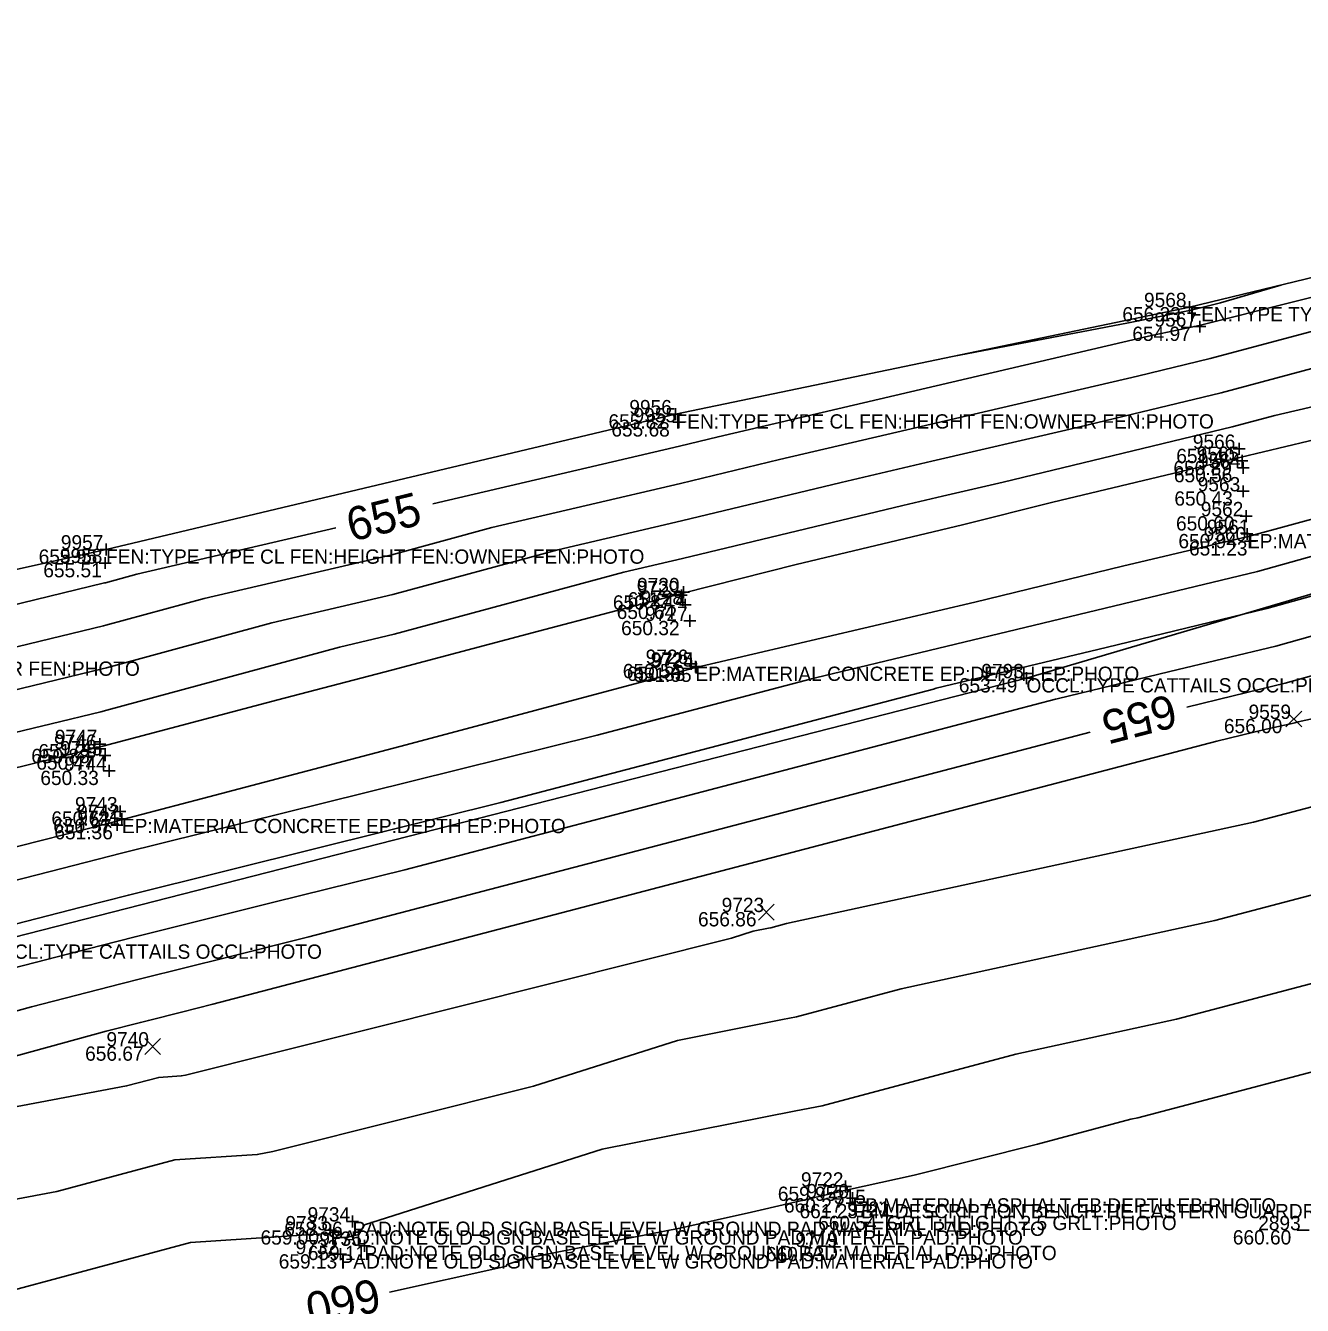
# Model space of a CAD drawing. Extents: x 2129350 to 2137777, y 657588 to 659885.
# Drawn here: x 2134161.5 to 2134268.7, y 659078.5 to 659185.9 of the extents above; entities that cross this region are included whole.
import ezdxf

# ---------------------------------------------------------------- set-up
doc = ezdxf.new("R2010")
doc.units = 0
for name, color, linetype in [('DT_X_Contour_Major', 7, 'Continuous'), ('DT_X_Contour_Minor', 7, 'Continuous'), ('DT_X_TIN_Hull', 7, 'Continuous'), ('SV_X_Occupation_Line', 7, 'Continuous'), ('SV_X_Random_Point', 7, 'Continuous'), ('SV_X_Shot_Marker', 7, 'Continuous'), ('SV_X_Text_Comment', 7, 'Continuous'), ('SV_X_Text_Elevation', 7, 'Continuous'), ('SV_X_Text_Name', 7, 'Continuous')]:
    doc.layers.add(name, color=color, linetype=linetype)

msp = doc.modelspace()

# ---------------------------------------------------------------- linework, layer by layer
at = {"layer": 'DT_X_Contour_Major'}
for points in [[(2134195.69, 659145.79), (2134216.4, 659150.64), (2134219.64, 659151.42), (2134235.81, 659155.2), (2134255.8, 659159.88), (2134260.05, 659160.76), (2134275.77, 659164.7), (2134292.78, 659169.65)], [(2134259.01, 659128.73), (2134262.9, 659129.67), (2134267.26, 659130.72), (2134272.2, 659132.1), (2134312.05, 659141.85), (2134315.24, 659142.75), (2134318.55, 659143.54), (2134356.18, 659152.33)], [(2134090.41, 659120), (2134090.8, 659120.09), (2134110.11, 659125.11), (2134111.21, 659125.37), (2134125.33, 659128.79), (2134129.5, 659129.8), (2134143.7, 659133.23), (2134147.32, 659134.1), (2134168.13, 659139.15), (2134168.2, 659139.17), (2134170.82, 659139.88), (2134187.54, 659143.78)], [(2134154.12, 659101.39), (2134162, 659103.56), (2134169.48, 659105.48), (2134171.25, 659105.93), (2134178.46, 659107.72), (2134185.28, 659109.42), (2134250.89, 659126.62)], [(2134192.04, 659079.6), (2134201.65, 659081.72), (2134201.85, 659081.78), (2134201.93, 659081.92), (2134203.56, 659082.44), (2134216.42, 659084.98), (2134222.44, 659086.3), (2134228.12, 659087.64), (2134230.5, 659088.18), (2134236.1, 659089.42), (2134246.48, 659092.02), (2134254.29, 659094.11), (2134254.9, 659094.24), (2134275.91, 659099.77), (2134289.22, 659102.85)]]:
    msp.add_lwpolyline(points, dxfattribs=at)
at = {"layer": 'DT_X_Contour_Minor'}
for points in [[(2134152.76, 659131.84), (2134168.03, 659135.54), (2134168.24, 659135.6), (2134176.5, 659137.84), (2134192.24, 659141.51), (2134200.65, 659143.79), (2134216.49, 659147.5), (2134224.81, 659149.5), (2134236.7, 659152.28), (2134254.85, 659156.52), (2134260.96, 659157.99), (2134275.77, 659161.94), (2134280.7, 659163.09), (2134300.56, 659168.43), (2134304.69, 659169.39), (2134308.74, 659170.44), (2134312.54, 659171.55), (2134332.75, 659176.79), (2134336.49, 659177.87), (2134356.95, 659183.17)], [(2134357, 659180.03), (2134343.97, 659176.66), (2134332.83, 659173.43), (2134320.38, 659170.2), (2134309.2, 659166.94), (2134306.79, 659166.32), (2134294.71, 659163.52), (2134282.62, 659160.26), (2134271.08, 659157.58), (2134261.88, 659155.12), (2134249.21, 659152.07), (2134237.6, 659149.36), (2134229.99, 659147.58), (2134216.57, 659144.35), (2134206.19, 659141.92), (2134192.34, 659138.17), (2134182.17, 659135.8), (2134168.28, 659132.03), (2134167.92, 659131.93), (2134158.21, 659129.58)], [(2134357.06, 659176.9), (2134351.46, 659175.45), (2134332.91, 659170.07), (2134328.21, 659168.85), (2134309.66, 659163.45), (2134308.89, 659163.25), (2134288.86, 659158.6), (2134284.53, 659157.44), (2134266.4, 659153.21), (2134262.8, 659152.25), (2134243.57, 659147.62), (2134238.49, 659146.44), (2134235.17, 659145.66), (2134216.66, 659141.21), (2134211.73, 659140.06), (2134192.45, 659134.84), (2134187.85, 659133.76), (2134168.32, 659128.46), (2134167.81, 659128.32), (2134163.65, 659127.32), (2134143.51, 659122.48)], [(2134354.27, 659172.9), (2134335.82, 659167.99), (2134332.96, 659167.27), (2134312.59, 659161.84), (2134310.18, 659161.23), (2134308.22, 659160.74), (2134295.76, 659157.65), (2134289.27, 659156.02), (2134287.68, 659155.64), (2134269.19, 659151.04), (2134263.57, 659149.7), (2134247.74, 659145.92), (2134240.17, 659144.03), (2134226.21, 659140.7), (2134216.67, 659138.28), (2134216.49, 659138.23), (2134204.56, 659135.1), (2134192.21, 659131.83), (2134182.68, 659129.32), (2134167.97, 659125.44), (2134167.73, 659125.38), (2134163.65, 659124.36), (2134152.8, 659121.69)], [(2134149.54, 659114.15), (2134168.53, 659118.99), (2134169.51, 659119.25), (2134176.36, 659121.06), (2134193.45, 659125.56), (2134215.07, 659131.32), (2134217.44, 659131.95), (2134217.78, 659132.04), (2134219.45, 659132.44), (2134241.19, 659137.52), (2134253.61, 659140.56), (2134264.15, 659143.06), (2134281.64, 659147.81), (2134287.19, 659149.33), (2134309.81, 659155.46), (2134311.1, 659155.81), (2134317.07, 659157.39), (2134335.2, 659162.28), (2134338.65, 659163.23), (2134359.31, 659168.81)], [(2134143.24, 659109.7), (2134164.52, 659115.16), (2134169.55, 659116.45), (2134190.08, 659121.55), (2134209.48, 659126.37), (2134227.5, 659131.1), (2134227.81, 659131.17), (2134246.92, 659135.78), (2134264.95, 659140.12), (2134285.42, 659145.84), (2134292.96, 659147.69), (2134312.13, 659153.08), (2134332.05, 659157.88), (2134341.43, 659160.07), (2134360.86, 659164.73)], [(2134239.34, 659158.16), (2134254.1, 659160.98), (2134259.36, 659162.06), (2134261.82, 659162.68), (2134266.91, 659164.16)], [(2134149.49, 659107.65), (2134166.17, 659111.93), (2134170.12, 659112.94), (2134186.21, 659116.94), (2134201.41, 659120.72), (2134237.74, 659130.24), (2134237.97, 659130.3), (2134252.24, 659133.74), (2134265.72, 659136.99), (2134281.01, 659141.26), (2134299.32, 659145.74), (2134313.17, 659149.64), (2134327.55, 659153.1), (2134348.69, 659158.03), (2134362.22, 659161.28)], [(2134155.75, 659105.6), (2134167.83, 659108.7), (2134170.68, 659109.44), (2134182.33, 659112.33), (2134193.34, 659115.07), (2134247.98, 659129.39), (2134248.13, 659129.43), (2134257.57, 659131.71), (2134266.49, 659133.85), (2134276.6, 659136.68), (2134305.69, 659143.8), (2134314.2, 659146.19), (2134323.05, 659148.32), (2134355.95, 659156)], [(2134127.59, 659090.34), (2134168.25, 659101.51), (2134171.13, 659102.25), (2134171.81, 659102.42), (2134174.59, 659103.11), (2134177.21, 659103.77), (2134261.53, 659125.87), (2134265.68, 659126.88), (2134267.84, 659127.35), (2134268.08, 659127.41), (2134268.35, 659127.48), (2134314.46, 659137.47), (2134316.66, 659137.98), (2134316.74, 659138), (2134318.98, 659138.61), (2134362.91, 659148.03)], [(2134154.98, 659094.1), (2134169.97, 659096.91), (2134172.67, 659097.63), (2134174.56, 659097.76), (2134174.91, 659097.83), (2134220.76, 659109.32), (2134222.58, 659109.9), (2134223.89, 659110.16), (2134224.07, 659110.19), (2134225.39, 659110.54), (2134264.61, 659119.07), (2134270.04, 659120.5), (2134276.27, 659121.94), (2134310.98, 659129.47), (2134318.67, 659131.25), (2134318.92, 659131.31), (2134326.75, 659133.45), (2134359.46, 659140.46)], [(2134127.31, 659081.14), (2134164.1, 659088.04), (2134174.01, 659090.7), (2134180.94, 659091.15), (2134182.24, 659091.4), (2134204.15, 659096.9), (2134216.24, 659100.74), (2134225.04, 659102.48), (2134226.23, 659102.72), (2134235.02, 659105.07), (2134261.37, 659110.8), (2134272, 659113.59), (2134284.19, 659116.41), (2134307.5, 659121.46), (2134320.67, 659124.52), (2134321.1, 659124.62), (2134334.51, 659128.28), (2134356.01, 659132.89)], [(2134158.23, 659079.17), (2134175.35, 659083.76), (2134186.81, 659084.51), (2134186.86, 659084.53), (2134187.34, 659084.2), (2134188.45, 659084.18), (2134189.48, 659084.43), (2134189.96, 659085.24), (2134209.9, 659091.59), (2134226.18, 659094.81), (2134228.38, 659095.24), (2134244.66, 659099.59), (2134258.14, 659102.52), (2134273.96, 659106.68), (2134292.11, 659110.88), (2134304.02, 659113.46), (2134322.68, 659117.79), (2134323.28, 659117.93), (2134342.28, 659123.12), (2134352.56, 659125.32)]]:
    msp.add_lwpolyline(points, dxfattribs=at)
at = {"layer": 'DT_X_TIN_Hull'}
msp.add_lwpolyline([(2134356.03, 659185.95), (2134303.52, 659173.01), (2134259.23, 659162.31), (2134216.07, 659153.31), (2134168.25, 659141.96), (2134125.88, 659132.55), (2134109.05, 659128.86), (2134056.89, 659117.03), (2133999.59, 659103.37), (2133973.21, 659091.25), (2133972.95, 659091.39), (2133971.1, 659091.46), (2133969.76, 659091.14), (2133967.6, 659091.08), (2133965.7, 659091.19), (2133965.45, 659091.23), (2133933.98, 659084.79), (2133923.28, 659083.03), (2133873.95, 659069.27), (2133819.31, 659054.81), (2133767.48, 659040.46), (2133725.98, 659030.57)], dxfattribs=at)
at = {"layer": 'SV_X_Occupation_Line'}
msp.add_lwpolyline([(2133964.23, 659050.82), (2133988.96, 659052.85), (2134023.9, 659066.14), (2134068.85, 659084.35), (2134158.11, 659108.79), (2134245.54, 659131.15), (2134308.77, 659149.81)], dxfattribs=at)
at = {"layer": 'SV_X_Random_Point'}
for p, q in [((2134267.33, 659127.06), (2134268.66, 659128.39)), ((2134267.33, 659128.39), (2134268.66, 659127.06)), ((2134223.03, 659110.84), (2134224.36, 659112.18)), ((2134223.03, 659112.18), (2134224.36, 659110.84)), ((2134171.5, 659099.56), (2134172.83, 659100.9)), ((2134171.5, 659100.9), (2134172.83, 659099.56))]:
    msp.add_line(p, q, dxfattribs=at)
at = {"layer": 'SV_X_Shot_Marker'}
for p, q in [((2134258.73, 659162.31), (2134259.73, 659162.31)), ((2134259.23, 659162.81), (2134259.23, 659161.81)), ((2134259.23, 659162.31), (2134259.23, 659162.31)), ((2134259.6, 659160.67), (2134260.6, 659160.67)), ((2134260.1, 659161.17), (2134260.1, 659160.17)), ((2134260.1, 659160.67), (2134260.1, 659160.67)), ((2134216.07, 659153.81), (2134216.07, 659152.81)), ((2134215.57, 659153.31), (2134216.57, 659153.31)), ((2134215.85, 659152.64), (2134216.85, 659152.64)), ((2134216.07, 659153.31), (2134216.07, 659153.31)), ((2134216.35, 659153.14), (2134216.35, 659152.14)), ((2134216.35, 659152.64), (2134216.35, 659152.64)), ((2134263.4, 659150.91), (2134263.4, 659149.91)), ((2134262.9, 659150.41), (2134263.9, 659150.41)), ((2134263.14, 659149.4), (2134264.14, 659149.4)), ((2134263.4, 659150.41), (2134263.4, 659150.41)), ((2134263.64, 659149.9), (2134263.64, 659148.9)), ((2134263.64, 659149.4), (2134263.64, 659149.4)), ((2134263.25, 659148.8), (2134264.25, 659148.8)), ((2134263.75, 659149.3), (2134263.75, 659148.3)), ((2134263.75, 659148.8), (2134263.75, 659148.8)), ((2134263.73, 659147.34), (2134263.73, 659146.34)), ((2134263.23, 659146.84), (2134264.23, 659146.84)), ((2134263.73, 659146.84), (2134263.73, 659146.84)), ((2134263.98, 659145.25), (2134263.98, 659144.25)), ((2134263.48, 659144.75), (2134264.48, 659144.75)), ((2134263.98, 659144.75), (2134263.98, 659144.75)), ((2134263.56, 659143.26), (2134264.56, 659143.26)), ((2134264.06, 659143.76), (2134264.06, 659142.76)), ((2134264.06, 659143.26), (2134264.06, 659143.26)), ((2134264.34, 659143.15), (2134264.34, 659142.15)), ((2134167.75, 659141.96), (2134168.75, 659141.96)), ((2134168.25, 659142.46), (2134168.25, 659141.46)), ((2134168.25, 659141.96), (2134168.25, 659141.96)), ((2134263.84, 659142.65), (2134264.84, 659142.65)), ((2134264.34, 659142.65), (2134264.34, 659142.65)), ((2134167.68, 659140.82), (2134168.68, 659140.82)), ((2134168.18, 659141.32), (2134168.18, 659140.32)), ((2134168.18, 659140.82), (2134168.18, 659140.82)), ((2134216.74, 659138.87), (2134216.74, 659137.87)), ((2134216.06, 659138.11), (2134217.06, 659138.11)), ((2134216.24, 659138.37), (2134217.24, 659138.37)), ((2134216.56, 659138.61), (2134216.56, 659137.61)), ((2134216.56, 659138.11), (2134216.56, 659138.11)), ((2134216.74, 659138.37), (2134216.74, 659138.37)), ((2134216.89, 659137.82), (2134216.89, 659136.82)), ((2134216.39, 659137.32), (2134217.39, 659137.32)), ((2134216.89, 659137.32), (2134216.89, 659137.32)), ((2134216.77, 659135.96), (2134217.77, 659135.96)), ((2134217.27, 659136.46), (2134217.27, 659135.46)), ((2134217.27, 659135.96), (2134217.27, 659135.96)), ((2134216.88, 659132.35), (2134217.88, 659132.35)), ((2134217.38, 659132.85), (2134217.38, 659131.85)), ((2134217.38, 659132.35), (2134217.38, 659132.35)), ((2134217.74, 659132.62), (2134217.74, 659131.62)), ((2134217.79, 659132.54), (2134217.79, 659131.54)), ((2134217.24, 659132.12), (2134218.24, 659132.12)), ((2134217.29, 659132.04), (2134218.29, 659132.04)), ((2134217.74, 659132.12), (2134217.74, 659132.12)), ((2134217.79, 659132.04), (2134217.79, 659132.04)), ((2134245.04, 659131.15), (2134246.04, 659131.15)), ((2134245.54, 659131.65), (2134245.54, 659130.65)), ((2134245.54, 659131.15), (2134245.54, 659131.15)), ((2134167.73, 659126.12), (2134167.73, 659125.12)), ((2134167.23, 659125.62), (2134168.23, 659125.62)), ((2134167.23, 659125.22), (2134168.23, 659125.22)), ((2134167.73, 659125.72), (2134167.73, 659124.72)), ((2134167.73, 659125.62), (2134167.73, 659125.62)), ((2134167.73, 659125.22), (2134167.73, 659125.22)), ((2134168.16, 659125.17), (2134168.16, 659124.17)), ((2134167.66, 659124.67), (2134168.66, 659124.67)), ((2134168.16, 659124.67), (2134168.16, 659124.67)), ((2134168.5, 659123.88), (2134168.5, 659122.88)), ((2134168, 659123.38), (2134169, 659123.38)), ((2134168.5, 659123.38), (2134168.5, 659123.38)), ((2134169.42, 659120.47), (2134169.42, 659119.47)), ((2134168.92, 659119.97), (2134169.92, 659119.97)), ((2134169.08, 659119.33), (2134170.08, 659119.33)), ((2134169.17, 659119.32), (2134169.17, 659118.32)), ((2134169.42, 659119.97), (2134169.42, 659119.97)), ((2134169.58, 659119.83), (2134169.58, 659118.83)), ((2134169.58, 659119.33), (2134169.58, 659119.33)), ((2134168.67, 659118.82), (2134169.67, 659118.82)), ((2134169.17, 659118.82), (2134169.17, 659118.82)), ((2134229.84, 659088.46), (2134230.84, 659088.46)), ((2134230.34, 659088.96), (2134230.34, 659087.96)), ((2134230.34, 659088.46), (2134230.34, 659088.46)), ((2134230.43, 659087.48), (2134231.43, 659087.48)), ((2134230.93, 659087.98), (2134230.93, 659086.98)), ((2134230.93, 659087.48), (2134230.93, 659087.48)), ((2134188.95, 659086.03), (2134188.95, 659085.03)), ((2134233.31, 659086.01), (2134234.31, 659086.01)), ((2134233.81, 659086.51), (2134233.81, 659085.51)), ((2134233.81, 659086.01), (2134233.81, 659086.01)), ((2134187.1, 659085.29), (2134187.1, 659084.29)), ((2134188.45, 659085.53), (2134189.45, 659085.53)), ((2134188.95, 659085.53), (2134188.95, 659085.53)), ((2134186.6, 659084.79), (2134187.6, 659084.79)), ((2134187.1, 659084.79), (2134187.1, 659084.79)), ((2134189.94, 659083.99), (2134189.94, 659082.99)), ((2134229.43, 659083.89), (2134229.43, 659082.89)), ((2134268.27, 659084.8), (2134269.27, 659084.8)), ((2134187.44, 659082.78), (2134188.44, 659082.78)), ((2134187.94, 659083.28), (2134187.94, 659082.28)), ((2134187.94, 659082.78), (2134187.94, 659082.78)), ((2134189.44, 659083.49), (2134190.44, 659083.49)), ((2134189.94, 659083.49), (2134189.94, 659083.49)), ((2134228.93, 659083.39), (2134229.93, 659083.39)), ((2134229.43, 659083.39), (2134229.43, 659083.39))]:
    msp.add_line(p, q, dxfattribs=at)

# ---------------------------------------------------------------- texts
at = {"layer": 'DT_X_Contour_Major'}
for s, rotation, p in [('655', 13.8795, (2134188.85, 659142.6)), ('655', 194.5841, (2134257.7, 659129.85)), ('660', 192.4338, (2134190.91, 659080.79))]:
    msp.add_text(s, height=2.8, rotation=rotation, dxfattribs=at).set_placement(p)
at = {"layer": 'SV_X_Text_Comment'}
for s, p in [('FEN:TYPE TYPE CL FEN:HEIGHT FEN:OWNER FEN:PHOTO', (2134259.23, 659161.11)), ('FEN:TYPE TYPE CL FEN:HEIGHT FEN:OWNER FEN:PHOTO', (2134216.07, 659152.11)), ('EP:MATERIAL CONCRETE EP:DEPTH EP:PHOTO', (2134264.06, 659142.06)), ('FEN:TYPE TYPE CL FEN:HEIGHT FEN:OWNER FEN:PHOTO', (2134168.25, 659140.76)), ('FEN:TYPE TYPE CL FEN:HEIGHT FEN:OWNER FEN:PHOTO', (2134125.88, 659131.35)), ('EP:MATERIAL CONCRETE EP:DEPTH EP:PHOTO', (2134217.74, 659130.92)), ('OCCL:TYPE CATTAILS OCCL:PHOTO', (2134245.54, 659129.95)), ('EP:MATERIAL CONCRETE EP:DEPTH EP:PHOTO', (2134169.58, 659118.14)), ('OCCL:TYPE CATTAILS OCCL:PHOTO', (2134158.11, 659107.59)), ('EB:MATERIAL ASPHALT EB:DEPTH EB:PHOTO', (2134230.93, 659086.28)), ('BM:DESCRIPTION BENCH TIE EASTERN GUARDRAIL POST BM:LOCATION BM:NOTE BM:PHOT', (2134231.64, 659085.8)), ('GRLT:HEIGHT 2.5 GRLT:PHOTO', (2134233.81, 659084.81)), ('PAD:NOTE OLD SIGN BASE LEVEL W GROUND PAD:MATERIAL PAD:PHOTO', (2134188.95, 659084.32)), ('PAD:NOTE OLD SIGN BASE LEVEL W GROUND PAD:MATERIAL PAD:PHOTO', (2134187.1, 659083.59)), ('PAD:NOTE OLD SIGN BASE LEVEL W GROUND PAD:MATERIAL PAD:PHOTO', (2134187.94, 659081.58)), ('PAD:NOTE OLD SIGN BASE LEVEL W GROUND PAD:MATERIAL PAD:PHOTO', (2134189.94, 659082.29))]:
    msp.add_text(s, height=1.2, dxfattribs=at).set_placement(p)
at = {"layer": 'SV_X_Text_Elevation'}
for s, p in [('656.23', (2134253.59, 659161.11)), ('654.97', (2134254.43, 659159.47)), ('655.82', (2134210.44, 659152.11)), ('655.68', (2134210.68, 659151.44)), ('650.89', (2134257.88, 659148.2)), ('651.40', (2134258.12, 659149.21)), ('650.56', (2134257.92, 659147.6)), ('650.43', (2134257.96, 659145.64)), ('650.60', (2134258.1, 659143.55)), ('650.94', (2134258.3, 659142.06)), ('655.95', (2134162.59, 659140.76)), ('651.23', (2134259.19, 659141.45)), ('655.51', (2134162.98, 659139.62)), ('650.87', (2134210.81, 659136.91)), ('651.14', (2134212.05, 659137.17)), ('650.64', (2134211.13, 659136.12)), ('650.32', (2134211.5, 659134.76)), ('650.54', (2134211.64, 659131.15)), ('650.83', (2134211.99, 659130.92)), ('651.05', (2134212.51, 659130.84)), ('653.49', (2134239.86, 659129.95)), ('656.00', (2134262.12, 659126.53)), ('650.88', (2134161.97, 659124.02)), ('650.47', (2134162.39, 659123.47)), ('651.29', (2134162.57, 659124.42)), ('650.33', (2134162.73, 659122.18)), ('650.62', (2134163.66, 659118.77)), ('650.97', (2134163.81, 659118.14)), ('651.36', (2134163.91, 659117.62)), ('656.86', (2134217.96, 659110.31)), ('656.67', (2134166.49, 659099.03)), ('659.95', (2134224.66, 659087.26)), ('660.27', (2134225.18, 659086.28)), ('661.23', (2134226.48, 659085.8)), ('660.54', (2134228.05, 659084.81)), ('658.96', (2134183.21, 659084.32)), ('659.00', (2134181.22, 659083.59)), ('660.60', (2134262.87, 659083.6)), ('659.13', (2134182.75, 659081.58)), ('659.11', (2134185.19, 659082.29)), ('660.53', (2134223.66, 659082.19))]:
    msp.add_text(s, height=1.2, dxfattribs=at).set_placement(p)
at = {"layer": 'SV_X_Text_Name'}
for s, p in [('9568', (2134255.41, 659162.31)), ('9567', (2134256.29, 659160.67)), ('9956', (2134212.19, 659153.31)), ('9955', (2134212.54, 659152.64)), ('9566', (2134259.51, 659150.41)), ('9565', (2134259.83, 659149.4)), ('9564', (2134259.95, 659148.8)), ('9563', (2134259.92, 659146.84)), ('9562', (2134260.18, 659144.75)), ('9561', (2134260.69, 659143.26)), ('9957', (2134164.45, 659141.96)), ('9560', (2134260.42, 659142.65)), ('9958', (2134164.37, 659140.82)), ('9729', (2134212.8, 659138.11)), ('9730', (2134212.84, 659138.37)), ('9728', (2134213.13, 659137.32)), ('9727', (2134213.52, 659135.96)), ('9726', (2134213.56, 659132.35)), ('9725', (2134213.99, 659132.12)), ('9724', (2134214.05, 659132.04)), ('9793', (2134241.75, 659131.15)), ('9559', (2134264.19, 659127.73)), ('9747', (2134163.95, 659125.62)), ('9746', (2134163.88, 659125.22)), ('9745', (2134164.38, 659124.67)), ('9744', (2134164.73, 659123.38)), ('9743', (2134165.64, 659119.97)), ('9742', (2134165.82, 659119.33)), ('9741', (2134165.83, 659118.82)), ('9723', (2134219.94, 659111.51)), ('9740', (2134168.28, 659100.23)), ('9722', (2134226.6, 659088.46)), ('9720', (2134227.07, 659087.48)), ('315', (2134229.37, 659087)), ('9721', (2134230.49, 659086.01)), ('9733', (2134183.31, 659084.79)), ('9734', (2134185.17, 659085.53)), ('2893', (2134265, 659084.8)), ('9732', (2134184.16, 659082.78)), ('9735', (2134186.15, 659083.49)), ('9719', (2134226.13, 659083.39))]:
    msp.add_text(s, height=1.2, dxfattribs=at).set_placement(p)

doc.saveas('drawing.dxf')
